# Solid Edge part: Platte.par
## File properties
Sűrűség: 0,000 kg/m^3
Pontosság: 0,990
Author: bmolnar
Last saved by: bmolnar
Revision: 78
Username: bmolnar
Dokumentum tartalom típus: 0
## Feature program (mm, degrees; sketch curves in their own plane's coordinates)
base feature "unnamed BaseFeature 1"
thread "unnamed Thread 1"
thread "unnamed Thread 2"
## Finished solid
Body 1: solid body, 65 faces, 114 edges, 62 vertices.
  Faces by surface: plane 38, cylinder 12, cone 10, torus 5
  Edges by curve: line 60, circle 36, spline 18
Bounding box of the edges (mm; curved faces can reach further): 167.000 x 50.000 x 14.000, from (-83.5, -25, 0) to (83.5, 25, 14).
Cylindrical faces by radius (mm): R3 x2, R3.5 x2, R4.188 x2, R5 x2, R5.5 x2, R9 x1, R15 x1
Conical faces (half-angle, radius in mm at the cone's reference point): 45 deg R3.6 x2, 45 deg R4.688 x4, 45 deg R15.25 x1, 60 deg R1.1547 x2, 60 deg R2.3094 x1
Toroidal faces (ring radius, tube radius in mm): R3.1 r0.1 x2, R4.4 r0.6 x2, R7.8 r1.2 x1
Planar faces by outward normal: +x 1, +y 4, +z 7, -x 1, -y 4, -z 5, oblique 16
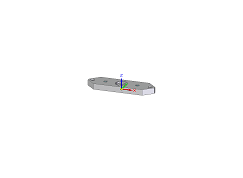
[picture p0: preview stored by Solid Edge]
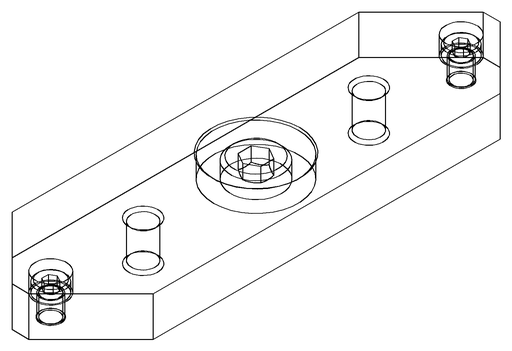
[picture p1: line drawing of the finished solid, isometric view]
